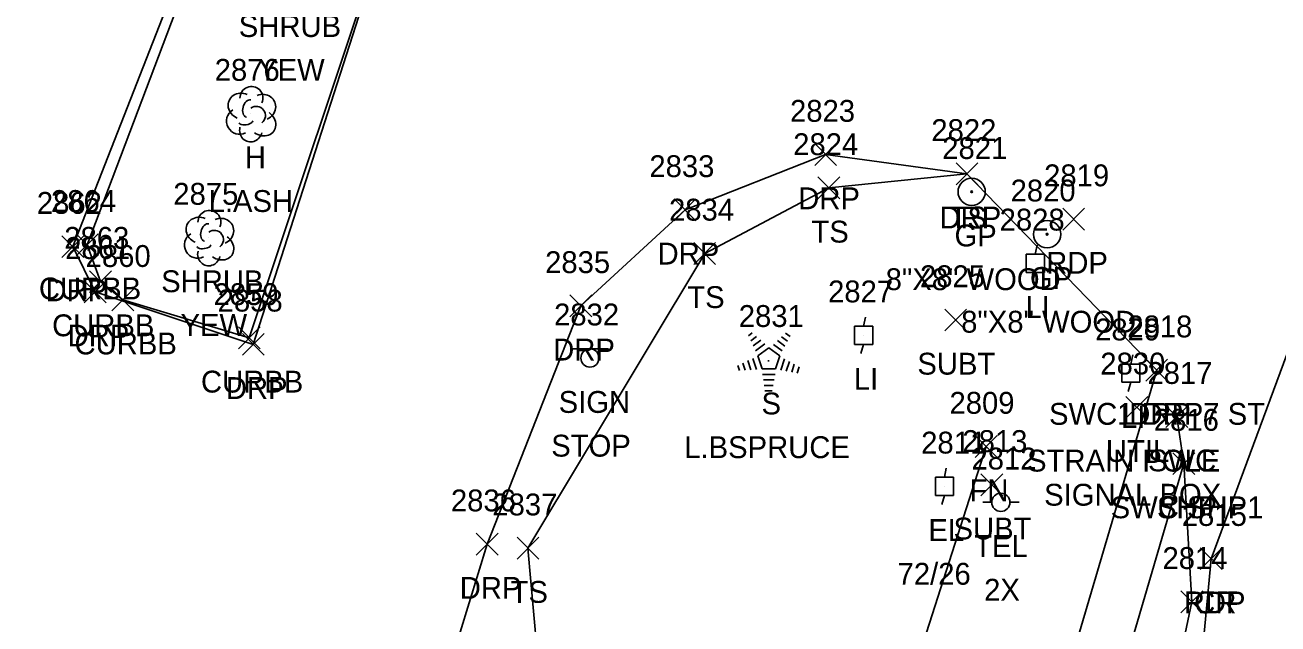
# Model space of a CAD drawing. Extents: x 1477930 to 1480780, y 774090 to 784647.
# Drawn here: x 1479402.4 to 1479517, y 775112.3 to 775167.1 of the extents above; entities that cross this region are included whole.
import ezdxf

# ---------------------------------------------------------------- set-up
doc = ezdxf.new("R2010")
doc.units = 0
for name, color, linetype in [('L_A', 7, 'Continuous'), ('L_C', 7, 'Continuous'), ('L_I', 7, 'Continuous'), ('L_TIC', 7, 'Continuous'), ('LELB', 7, 'Continuous'), ('LFNC', 7, 'Continuous'), ('LSH', 7, 'Continuous'), ('LTC', 7, 'Continuous'), ('LTD', 7, 'Continuous'), ('P_A', 7, 'Continuous'), ('P_I', 7, 'Continuous'), ('P_TIC', 7, 'Continuous'), ('PET', 7, 'Continuous'), ('PRC', 7, 'Continuous'), ('PSP', 7, 'Continuous'), ('R_A', 7, 'Continuous'), ('R_C', 7, 'Continuous'), ('R_I', 7, 'Continuous'), ('R_TIC', 7, 'Continuous'), ('RC', 7, 'Continuous'), ('RDP', 7, 'Continuous'), ('RGP', 7, 'Continuous'), ('RSW', 7, 'Continuous'), ('S_A', 7, 'Continuous'), ('S_C', 7, 'Continuous'), ('S_I', 7, 'Continuous'), ('SSGN', 7, 'Continuous'), ('U_A', 7, 'Continuous'), ('U_C', 7, 'Continuous'), ('U_I', 7, 'Continuous'), ('U_TIC', 7, 'Continuous'), ('UDEFAULT', 7, 'Continuous'), ('UEPT', 7, 'Continuous'), ('ULP', 7, 'Continuous'), ('UP', 7, 'Continuous')]:
    doc.layers.add(name, color=color, linetype=linetype)

msp = doc.modelspace()

# ---------------------------------------------------------------- linework, layer by layer
at = {"layer": 'L_TIC'}
for points in [[(1479487.58, 775152.52), (1479489.58, 775154.52)], [(1479489.58, 775152.52), (1479487.58, 775154.52)], [(1479474.94, 775151.23), (1479476.94, 775153.23)], [(1479476.94, 775151.23), (1479474.94, 775153.23)], [(1479463.58, 775145.24), (1479465.58, 775147.24)], [(1479465.58, 775145.24), (1479463.58, 775147.24)], [(1479489.33, 775127.57), (1479491.33, 775129.57)], [(1479491.33, 775127.57), (1479489.33, 775129.57)], [(1479447.41, 775118.27), (1479449.41, 775120.27)], [(1479449.41, 775118.27), (1479447.41, 775120.27)]]:
    msp.add_lwpolyline(points, dxfattribs=at)
at = {"layer": 'LELB'}
msp.add_lwpolyline([(1479488.58, 775153.52), (1479475.94, 775152.23), (1479464.58, 775146.24), (1479448.41, 775119.27), (1479451.69, 775082.69), (1479438.39, 775060.3), (1479422.89, 775054.64)], dxfattribs=at)
at = {"layer": 'LFNC'}
msp.add_lwpolyline([(1479373.09, 774875.08), (1479392.41, 774904.48), (1479409.31, 774932.95), (1479448.69, 775010.76), (1479458.93, 775035.46), (1479472.64, 775073.43), (1479490.33, 775128.57)], dxfattribs=at)
at = {"layer": 'LSH'}
msp.add_line((1479419.22, 775147.69), (1479419.22, 775147.69), dxfattribs=at)
msp.add_line((1479419.22, 775147.69), (1479419.22, 775147.69), dxfattribs=at)
msp.add_arc((1479419.26, 775149.12), 1.05, 335.5272, 180.9563, dxfattribs=at)
for centre, major_axis, ratio, start_param, end_param in [((1479418.42, 775148.35), (1.21, -0.51), 0.895232, 1.570796, 4.712389), ((1479420.26, 775148.27), (-1.14, -0.48), 0.949671, 1.570796, 4.712389), ((1479418.13, 775146.98), (0.58, -1.04), 0.959034, 3.141593, 6.283185), ((1479419.01, 775148.15), (-0.208, -0.792), 0.645439, 3.141593, 6.283185), ((1479419.72, 775147.52), (-0.5, 0.667), 0.989748, 3.141593, 6.283185), ((1479418.76, 775146.94), (-0.625, -0.083), 0.423636, 0, 3.141593), ((1479420.22, 775146.85), (-1.09, 0.79), 0.841452, 1.570796, 4.712389), ((1479419.22, 775146.19), (0.26, 1.06), 0.942809, 1.570796, 4.712389)]:
    msp.add_ellipse(centre, major_axis=major_axis, ratio=ratio, start_param=start_param, end_param=end_param, dxfattribs=at)
at = {"layer": 'LTC'}
for p, q in [((1479468.59, 775138.71), (1479468.94, 775138.97)), ((1479471.99, 775138.95), (1479472.41, 775138.65)), ((1479468.8, 775138.25), (1479469.33, 775138.63)), ((1479469.01, 775137.78), (1479469.71, 775138.29)), ((1479469.22, 775137.32), (1479470.09, 775137.96)), ((1479470.87, 775137.91), (1479471.68, 775137.32)), ((1479471.24, 775138.26), (1479471.92, 775137.76)), ((1479471.61, 775138.61), (1479472.16, 775138.21)), ((1479468.99, 775136.64), (1479469.32, 775135.62)), ((1479469.44, 775136.86), (1479470.45, 775137.6)), ((1479469.44, 775136.86), (1479469.83, 775135.67)), ((1479470.45, 775137.6), (1479471.45, 775136.87)), ((1479471.45, 775136.87), (1479471.06, 775135.67)), ((1479471.89, 775136.6), (1479471.55, 775135.56)), ((1479467.62, 775135.99), (1479467.77, 775135.53)), ((1479468.08, 775136.21), (1479468.29, 775135.56)), ((1479468.53, 775136.43), (1479468.8, 775135.59)), ((1479471.06, 775135.67), (1479469.83, 775135.67)), ((1479472.33, 775136.35), (1479472.04, 775135.47)), ((1479472.78, 775136.1), (1479472.54, 775135.37)), ((1479473.22, 775135.85), (1479473.03, 775135.28)), ((1479471.02, 775135.17), (1479469.88, 775135.17)), ((1479470.94, 775134.67), (1479469.95, 775134.67)), ((1479470.85, 775134.17), (1479470.02, 775134.17)), ((1479470.77, 775133.67), (1479470.09, 775133.67))]:
    msp.add_line(p, q, dxfattribs=at)
at = {"layer": 'LTD'}
msp.add_line((1479423.06, 775159.03), (1479423.06, 775159.03), dxfattribs=at)
msp.add_line((1479423.06, 775159.03), (1479423.06, 775159.03), dxfattribs=at)
msp.add_arc((1479423.11, 775160.46), 1.05, 335.5272, 180.9563, dxfattribs=at)
for centre, major_axis, ratio, start_param, end_param in [((1479422.27, 775159.7), (1.21, -0.51), 0.895232, 1.570796, 4.712389), ((1479424.1, 775159.61), (-1.14, -0.48), 0.949671, 1.570796, 4.712389), ((1479422.85, 775159.49), (-0.208, -0.792), 0.645439, 3.141593, 6.283185), ((1479423.56, 775158.86), (-0.5, 0.667), 0.989748, 3.141593, 6.283185), ((1479421.98, 775158.32), (0.58, -1.04), 0.959034, 3.141593, 6.283185), ((1479422.6, 775158.28), (-0.625, -0.083), 0.423636, 0, 3.141593), ((1479424.06, 775158.2), (-1.09, 0.79), 0.841452, 1.570796, 4.712389), ((1479423.06, 775157.53), (0.26, 1.06), 0.942809, 1.570796, 4.712389)]:
    msp.add_ellipse(centre, major_axis=major_axis, ratio=ratio, start_param=start_param, end_param=end_param, dxfattribs=at)
at = {"layer": 'P_TIC'}
for points in [[(1479497.34, 775148.38), (1479499.34, 775150.38)], [(1479499.34, 775148.38), (1479497.34, 775150.38)], [(1479507.43, 775126.01), (1479509.43, 775128.01)], [(1479509.43, 775126.01), (1479507.43, 775128.01)], [(1479509.93, 775117.31), (1479511.93, 775119.31)], [(1479511.93, 775117.31), (1479509.93, 775119.31)], [(1479509.93, 775117.31), (1479511.93, 775119.31)], [(1479511.93, 775117.31), (1479509.93, 775119.31)], [(1479508.16, 775113.37), (1479510.16, 775115.37)], [(1479510.16, 775113.37), (1479508.16, 775115.37)]]:
    msp.add_lwpolyline(points, dxfattribs=at)
at = {"layer": 'PET'}
msp.add_lwpolyline([(1479168.73, 774620.31), (1479212.4, 774655.38), (1479259.7, 774697.56), (1479293.15, 774732.73), (1479318.8, 774762.89), (1479333.57, 774781.21), (1479355.81, 774805.14), (1479380.51, 774839), (1479394.88, 774859.45), (1479419.72, 774898.43), (1479440.51, 774934.48), (1479462.36, 774978.06), (1479482.36, 775026.15), (1479497.52, 775065.91), (1479509.28, 775100.79), (1479510.93, 775118.31)], dxfattribs=at)
at = {"layer": 'PRC'}
msp.add_lwpolyline([(1479510.93, 775118.31), (1479531.61, 775174.16), (1479544.79, 775215.47), (1479560.12, 775265.14), (1479572.29, 775303.38)], dxfattribs=at)
at = {"layer": 'PSP'}
msp.add_lwpolyline([(1479333.57, 774781.21), (1479353.18, 774806.91), (1479376.82, 774840.34), (1479390.8, 774862.22), (1479415.7, 774900.26), (1479436.53, 774936.29), (1479458.59, 774979.44), (1479478.64, 775027.16), (1479495.22, 775066.68), (1479506.41, 775101.31), (1479509.16, 775114.37), (1479508.43, 775127.01)], dxfattribs=at)
at = {"layer": 'R_TIC'}
for points in [[(1479474.65, 775154.28), (1479476.65, 775156.28)], [(1479476.65, 775154.28), (1479474.65, 775156.28)], [(1479487.58, 775152.52), (1479489.58, 775154.52)], [(1479489.58, 775152.52), (1479487.58, 775154.52)], [(1479461.78, 775149.22), (1479463.78, 775151.22)], [(1479463.78, 775149.22), (1479461.78, 775151.22)], [(1479407.07, 775146.03), (1479409.07, 775148.03)], [(1479409.07, 775146.03), (1479407.07, 775148.03)], [(1479405.77, 775145.86), (1479407.77, 775147.86)], [(1479407.77, 775145.86), (1479405.77, 775147.86)], [(1479408.29, 775142.66), (1479410.29, 775144.66)], [(1479410.29, 775142.66), (1479408.29, 775144.66)], [(1479407.81, 775141.73), (1479409.81, 775143.73)], [(1479409.81, 775141.73), (1479407.81, 775143.73)], [(1479410.34, 775141), (1479412.34, 775143)], [(1479412.34, 775141), (1479410.34, 775143)], [(1479452.24, 775140.44), (1479454.24, 775142.44)], [(1479454.24, 775140.44), (1479452.24, 775142.44)], [(1479421.91, 775137.51), (1479423.91, 775139.51)], [(1479423.91, 775137.51), (1479421.91, 775139.51)], [(1479421.91, 775137.51), (1479423.91, 775139.51)], [(1479423.91, 775137.51), (1479421.91, 775139.51)], [(1479422.28, 775136.92), (1479424.28, 775138.92)], [(1479424.28, 775136.92), (1479422.28, 775138.92)], [(1479422.28, 775136.92), (1479424.28, 775138.92)], [(1479424.28, 775136.92), (1479422.28, 775138.92)], [(1479504.94, 775134.56), (1479506.94, 775136.56)], [(1479506.94, 775134.56), (1479504.94, 775136.56)], [(1479504.94, 775134.56), (1479506.94, 775136.56)], [(1479506.94, 775134.56), (1479504.94, 775136.56)], [(1479506.78, 775130.3), (1479508.78, 775132.3)], [(1479508.78, 775130.3), (1479506.78, 775132.3)], [(1479507.43, 775126.01), (1479509.43, 775128.01)], [(1479509.43, 775126.01), (1479507.43, 775128.01)], [(1479443.68, 775118.64), (1479445.68, 775120.64)], [(1479445.68, 775118.64), (1479443.68, 775120.64)]]:
    msp.add_lwpolyline(points, dxfattribs=at)
at = {"layer": 'RC'}
for points in [[(1479422.91, 775138.51), (1479411.34, 775142), (1479409.29, 775143.66), (1479408.07, 775147.03), (1479419.26, 775176.61), (1479421.02, 775179.12), (1479424.17, 775179.23), (1479435.29, 775175.65)], [(1479422.91, 775138.51), (1479435.29, 775175.65)]]:
    msp.add_lwpolyline(points, dxfattribs=at)
at = {"layer": 'RDP'}
for points in [[(1479423.28, 775137.92), (1479408.81, 775142.73), (1479406.77, 775146.86), (1479418.47, 775176.79), (1479420.43, 775179.72), (1479424.35, 775179.87), (1479435.51, 775175.94)], [(1479423.28, 775137.92), (1479435.51, 775175.94)], [(1479505.94, 775135.56), (1479488.58, 775153.52), (1479475.65, 775155.28), (1479462.78, 775150.22), (1479453.24, 775141.44), (1479444.68, 775119.64), (1479434.81, 775087.44), (1479422.89, 775054.64)]]:
    msp.add_lwpolyline(points, dxfattribs=at)
at = {"layer": 'RGP'}
for p, q in [((1479489.01, 775151.88), (1479489.01, 775151.88)), ((1479495.91, 775147.99), (1479495.91, 775147.99))]:
    msp.add_line(p, q, dxfattribs=at)
for centre, radius in [((1479489.01, 775151.88), 1.25), ((1479489.01, 775151.88), 0.0833), ((1479495.91, 775147.99), 1.25), ((1479495.91, 775147.99), 0.0833)]:
    msp.add_circle(centre, radius, dxfattribs=at)
at = {"layer": 'RSW'}
for points in [[(1479501.66, 775103.93), (1479497.13, 775105.7), (1479505.94, 775135.56)], [(1479501.66, 775103.93), (1479508.43, 775127.01), (1479507.78, 775131.3)]]:
    msp.add_lwpolyline(points, dxfattribs=at)
at = {"layer": 'SSGN'}
for p, q in [((1479452.44, 775137.5), (1479455.77, 775137.5)), ((1479454.08, 775136.67), (1479454.08, 775136.67))]:
    msp.add_line(p, q, dxfattribs=at)
msp.add_circle((1479454.08, 775136.67), 0.833, dxfattribs=at)
at = {"layer": 'U_TIC'}
for points in [[(1479486.54, 775139.15), (1479488.54, 775141.15)], [(1479488.54, 775139.15), (1479486.54, 775141.15)], [(1479489.85, 775124.07), (1479491.85, 775126.07)], [(1479491.85, 775124.07), (1479489.85, 775126.07)]]:
    msp.add_lwpolyline(points, dxfattribs=at)
at = {"layer": 'UDEFAULT'}
for points in [[(1479503.13, 775131.16), (1479505.13, 775133.16)], [(1479505.13, 775131.16), (1479503.13, 775133.16)]]:
    msp.add_lwpolyline(points, dxfattribs=at)
at = {"layer": 'UEPT'}
for p, q in [((1479486.69, 775126.6), (1479486.52, 775125.76)), ((1479485.69, 775124.1), (1479485.69, 775125.76)), ((1479485.69, 775125.76), (1479487.35, 775125.76)), ((1479487.35, 775125.76), (1479487.35, 775124.1)), ((1479487.35, 775124.1), (1479485.69, 775124.1)), ((1479486.27, 775123.26), (1479486.52, 775124.1)), ((1479486.52, 775124.93), (1479486.52, 775124.93))]:
    msp.add_line(p, q, dxfattribs=at)
at = {"layer": 'ULP'}
for p, q in [((1479495, 775146.99), (1479494.83, 775146.16)), ((1479494, 775144.49), (1479494, 775146.16)), ((1479494, 775146.16), (1479495.66, 775146.16)), ((1479495.66, 775146.16), (1479495.66, 775144.49)), ((1479495.66, 775144.49), (1479494, 775144.49)), ((1479494.58, 775143.66), (1479494.83, 775144.49)), ((1479494.83, 775145.33), (1479494.83, 775145.33)), ((1479479.29, 775140.42), (1479479.12, 775139.59)), ((1479478.29, 775137.92), (1479478.29, 775139.59)), ((1479478.29, 775139.59), (1479479.96, 775139.59)), ((1479479.12, 775138.76), (1479479.12, 775138.76)), ((1479479.96, 775139.59), (1479479.96, 775137.92)), ((1479479.96, 775137.92), (1479478.29, 775137.92)), ((1479478.87, 775137.09), (1479479.12, 775137.92)), ((1479503.75, 775136.95), (1479503.58, 775136.12)), ((1479502.75, 775134.45), (1479502.75, 775136.12)), ((1479502.75, 775136.12), (1479504.41, 775136.12)), ((1479504.41, 775136.12), (1479504.41, 775134.45)), ((1479504.41, 775134.45), (1479502.75, 775134.45)), ((1479503.33, 775133.62), (1479503.58, 775134.45)), ((1479503.58, 775135.28), (1479503.58, 775135.28))]:
    msp.add_line(p, q, dxfattribs=at)
at = {"layer": 'UP'}
for p, q in [((1479490.02, 775123.47), (1479490.85, 775123.47)), ((1479491.68, 775123.47), (1479491.68, 775123.47)), ((1479493.35, 775123.47), (1479492.51, 775123.47)), ((1479492.51, 775123.47), (1479492.51, 775123.47)), ((1479493.35, 775123.47), (1479493.35, 775123.47))]:
    msp.add_line(p, q, dxfattribs=at)
msp.add_circle((1479491.68, 775123.47), 0.833, dxfattribs=at)

# ---------------------------------------------------------------- texts
at = {"layer": 'L_A'}
for s, p in [('SHRUB', (1479421.95, 775166.04)), ('H', (1479422.5, 775154.03)), ('TS', (1479486.99, 775148.52)), ('TS', (1479474.35, 775147.23)), ('SHRUB', (1479414.85, 775142.69)), ('TS', (1479462.99, 775141.24)), ('S', (1479469.78, 775131.51)), ('FN', (1479488.81, 775123.57)), ('TS', (1479446.82, 775114.27))]:
    msp.add_text(s, height=2, dxfattribs=at).set_placement(p)
at = {"layer": 'L_C'}
for s, p in [('YEW', (1479423.72, 775162.04)), ('L.ASH', (1479419.19, 775150.03)), ('YEW', (1479416.62, 775138.69)), ('L.BSPRUCE', (1479462.71, 775127.51))]:
    msp.add_text(s, height=2, dxfattribs=at).set_placement(p)
at = {"layer": 'L_I'}
for s, p in [('2876', (1479419.75, 775162.03)), ('2822', (1479485.32, 775156.52)), ('2824', (1479472.68, 775155.23)), ('2875', (1479415.96, 775150.69)), ('2834', (1479461.32, 775149.24)), ('2831', (1479467.7, 775139.51)), ('2809', (1479486.98, 775131.57)), ('2837', (1479445.15, 775122.27))]:
    msp.add_text(s, height=2, dxfattribs=at).set_placement(p)
at = {"layer": 'LTC'}
msp.add_text('.', height=1.04, rotation=270, dxfattribs=at).set_placement((1479470.34, 775136.61))
at = {"layer": 'P_A'}
for s, p in [('RDP', (1479495.83, 775144.38)), ('SHP', (1479505.96, 775122.01)), ('RDP', (1479508.42, 775113.31)), ('CR', (1479509.37, 775113.31))]:
    msp.add_text(s, height=2, dxfattribs=at).set_placement(p)
at = {"layer": 'P_I'}
for s, p in [('2819', (1479495.64, 775152.38)), ('2816', (1479505.68, 775130.01)), ('2815', (1479508.24, 775121.31)), ('2815', (1479508.24, 775121.31)), ('2814', (1479506.47, 775117.37))]:
    msp.add_text(s, height=2, dxfattribs=at).set_placement(p)
at = {"layer": 'R_A'}
for s, p in [('DRP', (1479473.14, 775150.28)), ('DRP', (1479486.07, 775148.52)), ('GP', (1479487.44, 775146.88)), ('DRP', (1479460.27, 775145.22)), ('GP', (1479494.34, 775142.99)), ('CURBB', (1479403.66, 775142.03)), ('DRP', (1479404.26, 775141.86)), ('CURBB', (1479404.87, 775138.66)), ('DRP', (1479406.29, 775137.73)), ('CURBB', (1479406.92, 775137)), ('DRP', (1479450.72, 775136.44)), ('CURBB', (1479418.49, 775133.51)), ('CURBB', (1479418.49, 775133.51)), ('DRP', (1479420.77, 775132.92)), ('DRP', (1479420.77, 775132.92)), ('SWC1 DRP7 ST', (1479496.09, 775130.56)), ('DRP', (1479503.43, 775130.56)), ('SWC', (1479505.15, 775126.3)), ('SWC SHP1', (1479501.73, 775122.01)), ('DRP', (1479442.17, 775114.64))]:
    msp.add_text(s, height=2, dxfattribs=at).set_placement(p)
at = {"layer": 'R_C'}
for p in [(1479481.14, 775142.88), (1479488.05, 775138.99)]:
    msp.add_text('8"X8" WOOD', height=2, dxfattribs=at).set_placement(p)
at = {"layer": 'R_I'}
for s, p in [('2823', (1479472.39, 775158.28)), ('2822', (1479485.32, 775156.52)), ('2821', (1479486.32, 775154.88)), ('2833', (1479459.52, 775153.22)), ('2820', (1479492.57, 775150.99)), ('2862', (1479403.47, 775149.86)), ('2864', (1479404.77, 775150.03)), ('2863', (1479405.98, 775146.66)), ('2861', (1479406.07, 775145.73)), ('2860', (1479407.94, 775145)), ('2835', (1479449.98, 775144.44)), ('2859', (1479419.64, 775141.51)), ('2859', (1479419.64, 775141.51)), ('2858', (1479420.02, 775140.92)), ('2858', (1479420.02, 775140.92)), ('2818', (1479503.25, 775138.56)), ('2818', (1479503.25, 775138.56)), ('2817', (1479505.09, 775134.3)), ('2816', (1479505.68, 775130.01)), ('2836', (1479441.36, 775122.64))]:
    msp.add_text(s, height=2, dxfattribs=at).set_placement(p)
at = {"layer": 'S_A'}
msp.add_text('SIGN', height=2, dxfattribs=at).set_placement((1479451.22, 775131.65))
at = {"layer": 'S_C'}
msp.add_text('STOP', height=2, dxfattribs=at).set_placement((1479450.54, 775127.65))
at = {"layer": 'S_I'}
msp.add_text('2832', height=2, dxfattribs=at).set_placement((1479450.8, 775139.65))
at = {"layer": 'U_A'}
for s, p in [('LI', (1479493.93, 775140.33)), ('SUBT', (1479484.04, 775135.15)), ('LI', (1479478.23, 775133.76)), ('LI', (1479502.68, 775130.28)), ('UTIL', (1479501.29, 775127.16)), ('EL', (1479485.05, 775119.93)), ('SUBT', (1479487.35, 775120.07)), ('TEL', (1479489.24, 775118.47))]:
    msp.add_text(s, height=2, dxfattribs=at).set_placement(p)
at = {"layer": 'U_C'}
for s, p in [('STRAIN POLE', (1479494.08, 775126.28)), ('SIGNAL BOX', (1479495.64, 775123.16)), ('72/26', (1479482.23, 775115.93)), ('2X', (1479490.15, 775114.47))]:
    msp.add_text(s, height=2, dxfattribs=at).set_placement(p)
at = {"layer": 'U_I'}
for s, p in [('2828', (1479491.57, 775148.33)), ('2825', (1479484.28, 775143.15)), ('2827', (1479475.87, 775141.76)), ('2829', (1479500.31, 775138.28)), ('2830', (1479500.78, 775135.16)), ('2811', (1479484.39, 775127.93)), ('2813', (1479488.16, 775128.07)), ('2812', (1479488.99, 775126.47))]:
    msp.add_text(s, height=2, dxfattribs=at).set_placement(p)

doc.saveas('drawing.dxf')
